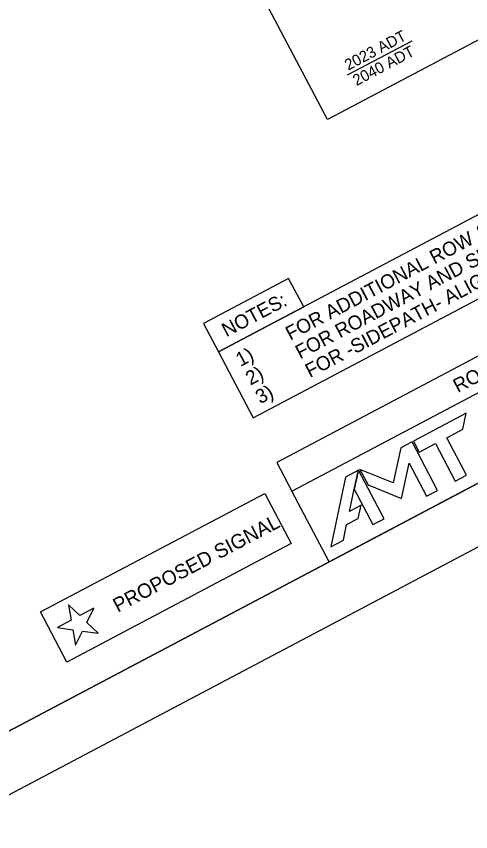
# Model space of a CAD drawing. Extents: x 1486990 to 1489232, y 497582 to 499336.
# Drawn here: x 1488614.3 to 1488796, y 498121.1 to 498447.2 of the extents above; entities that cross this region are included whole.
import ezdxf

# ---------------------------------------------------------------- set-up
doc = ezdxf.new("R2010")
doc.units = 0
for name, color, linetype in [('PROF-AXIS', 7, 'Continuous'), ('PROF-MAJR-LABL', 7, 'Continuous'), ('Prop Drainage Ditch Boundaries', 7, 'Continuous'), ('Prop Drainage Structure Catch Basin Open Throat 1 CELL', 7, 'Continuous'), ('Prop Drainage Structure Pipe Alternate 15in', 7, 'Continuous'), ('Prop Drainage Structure Plot Symbol 20 Scale', 7, 'Continuous'), ('Prop Earthen Structure V Ditch Berm Detail CELL', 7, 'Continuous'), ('Typical Terminator CELL', 7, 'Continuous')]:
    doc.layers.add(name, color=color, linetype=linetype)

msp = doc.modelspace()

# ---------------------------------------------------------------- linework, layer by layer
at = {"layer": 'PROF-AXIS'}
msp.add_line((1488746.72, 498423.79), (1488772.56, 498437.44), dxfattribs=at)
at = {"layer": 'PROF-MAJR-LABL'}
msp.add_lwpolyline([(1488636.25, 498205.74), (1488630.72, 498202.82), (1488636.91, 498201.93), (1488637.99, 498195.75), (1488640.75, 498201.38), (1488646.95, 498200.5), (1488642.46, 498204.86), (1488645.22, 498210.48), (1488639.68, 498207.55), (1488635.18, 498211.92), (1488636.25, 498205.74)], dxfattribs=at)
at = {"layer": 'Prop Drainage Ditch Boundaries'}
msp.add_lwpolyline([(1487562.23, 497581.96), (1489050.94, 498368.04), (1488539.66, 499336.34), (1487050.94, 498550.27)], close=True, dxfattribs=at)
at = {"layer": 'Prop Drainage Structure Catch Basin Open Throat 1 CELL'}
for points in [[(1488535.14, 499308.53), (1487208.67, 498608.12), (1487698.94, 497679.61), (1489025.4, 498380.01)], [(1487698.94, 497679.61), (1487208.66, 498608.09), (1488358.21, 499215.12), (1488428.29, 499082.43), (1488605.19, 499175.82), (1489025.4, 498380.01)]]:
    msp.add_lwpolyline(points, close=True, dxfattribs=at)
at = {"layer": 'Prop Drainage Structure Plot Symbol 20 Scale'}
msp.add_lwpolyline([(1487208.67, 498608.09), (1488222.08, 499143.23), (1488965.38, 498493.69), (1489025.4, 498380.01), (1487698.95, 497679.62)], close=True, dxfattribs=at)
at = {"layer": 'Prop Earthen Structure V Ditch Berm Detail CELL'}
for points in [[(1488671.68, 498532.92), (1488879.76, 498642.79), (1488946.84, 498515.75), (1488738.76, 498405.88)], [(1488709.02, 498286.64), (1488994.97, 498437.63), (1488981.06, 498463.98), (1488695.11, 498312.99)], [(1488724.52, 498257.28), (1488920.87, 498360.95), (1488914.78, 498372.49), (1488718.43, 498268.81)], [(1488724.52, 498257.28), (1488920.87, 498360.95), (1488935.79, 498332.69), (1488739.44, 498229.02)], [(1488695.11, 498312.99), (1488729.22, 498331), (1488723.2, 498342.4), (1488689.09, 498324.39)], [(1488623.9, 498209), (1488713.68, 498256.4), (1488724.24, 498236.4), (1488634.46, 498189)]]:
    msp.add_lwpolyline(points, close=True, dxfattribs=at)
at = {"layer": 'Typical Terminator CELL'}
msp.add_lwpolyline([(1488724.52, 498257.28), (1488920.87, 498360.95), (1488935.79, 498332.69), (1488739.44, 498229.02)], close=True, dxfattribs=at)
for points in [[(1488794.32, 498263.7), (1488786.42, 498278.66), (1488792.87, 498282.06), (1488794.24, 498288.48), (1488773.12, 498277.33), (1488775.47, 498272.88), (1488781.97, 498276.31), (1488789.87, 498261.35), (1488794.32, 498263.7)], [(1488768.3, 498254.33), (1488771.35, 498268.51), (1488778.35, 498255.26), (1488782.8, 498257.61), (1488772.55, 498277.03), (1488768.1, 498274.68), (1488764.97, 498260.63), (1488751.69, 498266.02), (1488754.96, 498259.83), (1488768.3, 498254.33)], [(1488749.42, 498258.14), (1488751.12, 498265.71), (1488745.92, 498262.97), (1488740.05, 498235.04), (1488745.09, 498237.7), (1488746.41, 498243.98), (1488751.02, 498246.41), (1488752.25, 498251.76), (1488747.48, 498249.24), (1488749.42, 498258.14)], [(1488761.37, 498246.3), (1488751.12, 498265.71), (1488749.42, 498258.14), (1488756.92, 498243.95), (1488761.37, 498246.3)]]:
    msp.add_lwpolyline(points, dxfattribs=at)

# ---------------------------------------------------------------- texts
at = {"layer": 'PROF-AXIS'}
for s, height, rotation, p in [('2023 ADT', 4.444, 27.8404, (1488747.05, 498425.44)), ('2040 ADT', 4.444, 27.8404, (1488750.32, 498419.25)), ('PROPOSED SIGNAL', 5.75, 27.8351, (1488654.86, 498208.64))]:
    msp.add_text(s, height=height, rotation=rotation, dxfattribs=at).set_placement(p)
at = {"layer": 'Prop Drainage Structure Pipe Alternate 15in'}
for s, p in [('FOR ADDITIONAL ROW & EASEMENT INFORMATION SEE SHEET 4A.', (1488723.84, 498317.46)), ('FOR ROADWAY AND SIDEPATH PROFILES SEE SHEETS 6 THRU 8.', (1488727.78, 498310)), ('FOR -SIDEPATH- ALIGNMENT DETAIL SEE SHEETS 2B-1 & 2B-2.', (1488731.72, 498302.54)), ('NOTES:', (1488698.31, 498318.79)), ('ROADWAY DESIGN', (1488790.87, 498296.5)), ('1)', (1488703.94, 498306.96)), ('2)', (1488707.88, 498299.5)), ('3)', (1488711.82, 498292.03))]:
    msp.add_text(s, height=5.625, rotation=27.8351, dxfattribs=at).set_placement(p)

doc.saveas('drawing.dxf')
